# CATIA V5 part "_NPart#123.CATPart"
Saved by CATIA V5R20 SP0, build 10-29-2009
Part number: 1BOLAØ2,3
Revision: ANY
Definition: UNKNOWN
Nomenclature: 1BOLAØ2,3
Source: Unknown
Bounding box of the stored display mesh (mm): x -1.19 to 1.19, y -1.19 to 1.19, z -1.19 to 1.19
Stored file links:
  C:\Users\Utente\Desktop\IO LAVORO\3D X SITO CF\CUMSA\3D files AE\AE 082430\_NPart#123.CATPart
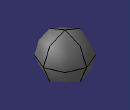
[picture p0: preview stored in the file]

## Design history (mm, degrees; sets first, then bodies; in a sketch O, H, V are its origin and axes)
Body1 "Revolución1" (main body)
  Solid1: solid without history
